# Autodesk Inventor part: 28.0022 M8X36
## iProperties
Created: 2006-02
Part Number: 28.0022 M8X36
Material: Steel, Mild
Description: Cylinder Head Cap Screw
Document SubType Name: Modeling
Standard: DIN 7984
Designer: Andy Moles
Standards Organization: DIN
Language: en-US
Size Designation: M8 x 35
Categories: <MemberInstance><Categories><Category DisplayName="Fasteners" InternalName="e4da775c-781d-43d5-af7c-5136215cf5a6" Mnemonic="FSTN"><Category DisplayName="Bolts"
Mass: 17.5851 g
Surface Area: 13.9339 cm^2
Volume: 2.23729 cm^3
Density: 7.86 g/cm^3
Author: Andy Moles
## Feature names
1. Body [Revolution]
2. Slot [Extrusion]
3. Chamfer1
